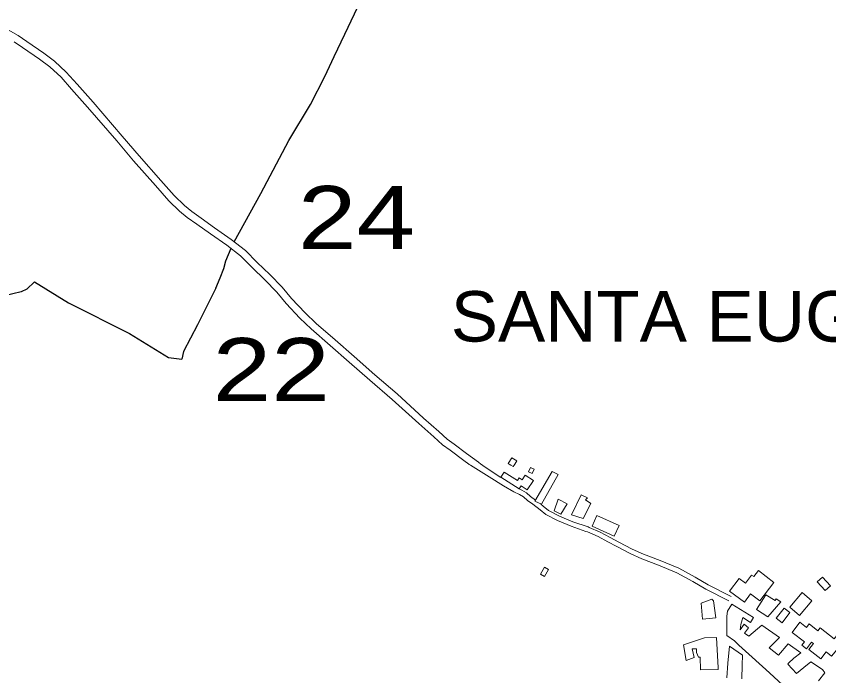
# Model space of a CAD drawing. Extents: x 476989 to 498418, y 4381813 to 4416555.
# Drawn here: x 485600 to 486244, y 4386277 to 4386800 of the extents above; entities that cross this region are included whole.
import ezdxf
from ezdxf.enums import TextEntityAlignment as Align

# ---------------------------------------------------------------- set-up
doc = ezdxf.new("R2010")
doc.units = 0
doc.header["$LTSCALE"] = 20
for name, color, linetype, lineweight in [('13', 7, 'Continuous', 13), ('36', 7, 'Continuous', 13), ('47', 7, 'Continuous', 13), ('6', 7, 'Continuous', 25)]:
    doc.layers.add(name, color=color, linetype=linetype, lineweight=lineweight)
doc.layers.add('7', color=7, linetype='Continuous')

msp = doc.modelspace()

# ---------------------------------------------------------------- linework, layer by layer
at = {"layer": '36'}
for p, q in [((485958.73, 4386444.52), (485959.23, 4386444.17)), ((485959.23, 4386444.17), (485960.09, 4386443.64)), ((485968.47, 4386444.51), (485969.59, 4386443.62)), ((485969.59, 4386443.62), (485969.89, 4386443.38))]:
    msp.add_line(p, q, dxfattribs=at)
for points in [[(485574.47, 4386799.34), (485601.49, 4386784.39), (485608.29, 4386779.54), (485621.78, 4386770.31), (485630.2, 4386764.12), (485639.68, 4386755.33), (485648.17, 4386745.82), (485660.98, 4386731.48), (485684.06, 4386704.54), (485697.45, 4386688.93), (485714.72, 4386669.33), (485725.09, 4386657.39), (485733.36, 4386649.47), (485739.11, 4386644.68), (485746.54, 4386639.47), (485757.24, 4386631.89), (485770.36, 4386622.7), (485781.69, 4386613.91), (485791.03, 4386604.44), (485801.13, 4386594.74), (485810.85, 4386584.65), (485818.25, 4386575.74), (485829.07, 4386564.32), (485837.71, 4386556.08), (485852.8, 4386542.97), (485867.86, 4386529.7), (485884.28, 4386515.38), (485901.98, 4386500.14), (485923.03, 4386480.92), (485935.07, 4386470.44), (485941.64, 4386464.26), (485947.14, 4386460.32), (485956.97, 4386452.87), (485966.63, 4386445.97), (485968.47, 4386444.51)], [(485598.37, 4386779.45), (485604.95, 4386774.75), (485618.4, 4386765.55), (485626.48, 4386759.62), (485635.51, 4386751.24), (485643.81, 4386741.94), (485656.59, 4386727.64), (485679.63, 4386700.74), (485693.05, 4386685.1), (485710.33, 4386665.49), (485720.86, 4386653.36), (485729.47, 4386645.11), (485735.56, 4386640.04), (485743.18, 4386634.7), (485753.88, 4386627.12), (485766.9, 4386618), (485777.81, 4386609.54), (485786.93, 4386600.29), (485797.01, 4386590.61), (485806.5, 4386580.76), (485813.89, 4386571.86), (485824.94, 4386560.19), (485833.78, 4386551.77), (485848.96, 4386538.58), (485864.01, 4386525.31), (485880.46, 4386510.97), (485898.1, 4386495.78), (485919.15, 4386476.56), (485931.15, 4386466.11), (485937.93, 4386459.74), (485943.93, 4386455.44), (485954.79, 4386447.35), (485958.73, 4386444.52)], [(485960.09, 4386443.64), (485972.91, 4386435.65), (485974.99, 4386434.48)], [(485969.89, 4386443.38), (485974.94, 4386439.93), (485984.36, 4386433.94)], [(485974.99, 4386434.48), (485986.32, 4386427.31), (485994.65, 4386422.54), (485998.97, 4386420.3), (486002.25, 4386418.45), (486005.36, 4386415.71), (486009.59, 4386412.64), (486015.46, 4386408.13), (486019.91, 4386404.47), (486029.22, 4386399.61), (486040.03, 4386395.1), (486051.72, 4386391.11)], [(485998.78, 4386424.94), (486000.81, 4386423.66), (486004.47, 4386421.63), (486007.76, 4386418.78), (486011.73, 4386415.89)], [(486053.43, 4386394.57), (486041.36, 4386398.68), (486030.81, 4386403.08), (486022.01, 4386407.71), (486017.89, 4386411.18), (486016, 4386412.63)], [(486166.79, 4386339.38), (486148.76, 4386348.75), (486138.31, 4386354.74), (486125.51, 4386361.79), (486110.65, 4386367.88), (486097.4, 4386373), (486088.44, 4386376.94), (486077.92, 4386382.5), (486070.93, 4386386.27), (486062.96, 4386390.53), (486054.41, 4386394.18), (486053.43, 4386394.57)], [(486165.01, 4386335.95), (486146.91, 4386345.36), (486136.42, 4386351.37), (486123.84, 4386358.3), (486109.22, 4386364.29), (486095.93, 4386369.43), (486086.76, 4386373.46), (486076.11, 4386379.09), (486069.11, 4386382.87), (486061.29, 4386387.04), (486052.94, 4386390.61), (486051.72, 4386391.11)]]:
    msp.add_lwpolyline(points, dxfattribs=at)
at = {"layer": '47'}
for p, q in [((485990.9, 4386444.46), (485992.28, 4386443.57)), ((485994.78, 4386443.57), (485995.35, 4386444.45))]:
    msp.add_line(p, q, dxfattribs=at)
for points in [[(485993.01, 4386449.5), (485990.09, 4386444.99), (485990.9, 4386444.46)], [(485995.35, 4386444.45), (485996.96, 4386446.94), (485993.01, 4386449.5)], [(485992.28, 4386443.57), (485994.04, 4386442.43), (485994.78, 4386443.57)], [(486207.89, 4386269.11), (486197.22, 4386278.94), (486183.52, 4386291.37), (486172.92, 4386300.75), (486169.52, 4386304.18), (486163.43, 4386308.62), (486163.35, 4386323.92), (486163.86, 4386327.82), (486167.31, 4386333.4), (486184.57, 4386322.72), (486182.19, 4386318.85), (486176.16, 4386322.77), (486174.66, 4386317.23), (486173.92, 4386313.12), (486177.21, 4386317.42), (486180.62, 4386314.52), (486177.41, 4386310.29), (486180.98, 4386307.91), (486191.16, 4386316.77), (486205.13, 4386306.89), (486197.06, 4386298.75), (486204.33, 4386293.02), (486212.03, 4386301.77), (486222.21, 4386294.87), (486216.6, 4386290.52), (486212.26, 4386286.61), (486211.73, 4386285.71), (486218.75, 4386278.48), (486224.6, 4386283.13), (486229.99, 4386287.63), (486239.2, 4386281.49), (486241.12, 4386278.91), (486236.15, 4386272.68)], [(486163.32, 4386274.85), (486164.31, 4386286.47), (486165.48, 4386300.11), (486175.89, 4386292.83), (486175.7, 4386284.88), (486175.47, 4386274.15)]]:
    msp.add_lwpolyline(points, dxfattribs=at)
for points in [[(486007.84, 4386441.78), (486006.17, 4386438.43), (486008.97, 4386437.04), (486010.64, 4386440.39)], [(485984.24, 4386434.17), (485998.74, 4386424.88), (486000.25, 4386427.24), (486005.23, 4386424.05), (486010.03, 4386431.55), (486003.62, 4386435.64), (486001.24, 4386431.91), (485998.8, 4386433.45), (485997.55, 4386431.47), (485986.89, 4386438.17)], [(486011.2, 4386414.95), (486025.05, 4386438.61), (486029.67, 4386436.29), (486016.57, 4386412.69)], [(486036.76, 4386412.93), (486031.69, 4386404.67), (486026.63, 4386407.3), (486029.76, 4386416.71)], [(486040.31, 4386404.1), (486047.89, 4386420.05), (486052.89, 4386417.8), (486051.44, 4386416.1), (486055.67, 4386413.11), (486049.58, 4386401.34)], [(486056.54, 4386395.24), (486074.12, 4386387.23), (486078.01, 4386395.76), (486060.43, 4386403.77)], [(486018.93, 4386362.69), (486015.77, 4386357.05), (486018.83, 4386355.33), (486021.99, 4386360.97)], [(486177.46, 4386334.9), (486165.66, 4386343.78), (486173.16, 4386353.75), (486178.14, 4386349.99), (486183.04, 4386356.48), (486184.75, 4386355.18), (486188.44, 4386360.04), (486200.81, 4386350.64), (486189.64, 4386335.95), (486182.1, 4386341.66)], [(486235.17, 4386351.11), (486241.47, 4386344.22), (486245.56, 4386347.96), (486239.26, 4386354.85)], [(486154.63, 4386322.62), (486152.94, 4386336.08), (486151.54, 4386337.3), (486143.16, 4386334.27), (486144.18, 4386321.35)], [(486195.91, 4386323.31), (486186.91, 4386329.06), (486194.4, 4386340.79), (486201.65, 4386336.15), (486202.52, 4386337.51), (486206.25, 4386335.11)], [(486230.98, 4386336.09), (486221.02, 4386324.35), (486213.35, 4386330.86), (486223.31, 4386342.6)], [(486202.64, 4386322.24), (486208.94, 4386330.25), (486213.51, 4386326.66), (486207.21, 4386318.65)], [(486215.39, 4386310.95), (486225.04, 4386303.46), (486222.96, 4386300.79), (486226.53, 4386298), (486230.66, 4386303.29), (486232.12, 4386302.14), (486228.44, 4386297.48), (486237.88, 4386290.02), (486242.19, 4386295.47), (486246.52, 4386292.02), (486251.95, 4386298.84), (486257.84, 4386294.14), (486264.24, 4386302.16), (486252.81, 4386311.27), (486248.48, 4386305.84), (486237.37, 4386314.68), (486235.51, 4386312.34), (486228.81, 4386317.66), (486226.55, 4386314.82), (486221.28, 4386318.99)], [(486155.38, 4386307.01), (486156.54, 4386282.98), (486156.52, 4386281.63), (486142.48, 4386281.38), (486142.25, 4386291.36), (486140.97, 4386291.3), (486139.52, 4386294.93), (486139.27, 4386298.01), (486135.89, 4386297.83), (486137.52, 4386291.13), (486131.33, 4386288.74), (486129.03, 4386301.08), (486145.69, 4386306.69)]]:
    msp.add_lwpolyline(points, close=True, dxfattribs=at)
at = {"layer": '6'}
for points in [[(485772.9, 4386620.73), (485793.92, 4386659.02), (485816.04, 4386701.22), (485833.41, 4386729.64), (485844.8, 4386751.93), (485852.09, 4386767.68), (485860.52, 4386785.33), (485878.39, 4386823.62), (485889.18, 4386844.24)], [(485770.04, 4386615.49), (485765.93, 4386605.5), (485764.36, 4386599.24), (485761.42, 4386591.8), (485757.89, 4386583.77)], [(485614.42, 4386588.88), (485608.24, 4386583.25), (485603.79, 4386581.02), (485590.67, 4386577.99), (485569.57, 4386574.82), (485555.53, 4386573.67), (485552.14, 4386573.42), (485549.36, 4386573.22), (485546.88, 4386573.26), (485541.5, 4386573.42), (485538.28, 4386574.27), (485529.3, 4386577.31), (485524.93, 4386579.57), (485522.13, 4386581.47), (485519.82, 4386582.6), (485513.12, 4386583.13), (485507.1, 4386583.36), (485502.68, 4386583.42), (485498.06, 4386583.56), (485495.44, 4386583.92), (485492.88, 4386586.05)], [(485614.42, 4386588.88), (485641.39, 4386572.37), (485689.82, 4386547.96), (485720.72, 4386529.08), (485731.35, 4386527.79)], [(485758.23, 4386584.1), (485743.68, 4386554.82), (485732.57, 4386533.82), (485731.35, 4386527.79)]]:
    msp.add_lwpolyline(points, dxfattribs=at)

# ---------------------------------------------------------------- texts
at = {"layer": '13', "width": 1.25}
for s, p in [('24', (485869.79, 4386615.04)), ('22', (485802.15, 4386494.43))]:
    msp.add_text(s, height=50, dxfattribs=at).set_placement(p, align=Align.CENTER)
at = {"layer": '7', "width": 1.05}
msp.add_text('SANTA EUGÈNIA', height=40, dxfattribs=at).set_placement((486172.38, 4386541.63), align=Align.CENTER)

doc.saveas('drawing.dxf')
